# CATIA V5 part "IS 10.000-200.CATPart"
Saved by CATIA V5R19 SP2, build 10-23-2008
Part number: IS 10.000-200
Bounding box of the stored display mesh (mm): x -97.324 to 97.324, y -97.5 to 97.5, z 0 to 560
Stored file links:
  C:\Users\Bora\Desktop\3D Katı model\IS serisi\IS 10.000\IS 10.000-200.CATPart
  C:\Program Files\Dassault Systemes\B19\intel_a\reffiles\standard\MetricThickPitch.txt
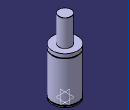
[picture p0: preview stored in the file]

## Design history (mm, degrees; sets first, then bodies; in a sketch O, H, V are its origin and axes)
Body1 (main body)
  Sketch1 on yz-plane, origin (0, 0, 0), H (0, 1, 0), V (0, 0, 1)
    point P1 (97.5, 329)
    point P4 (97.5, 324)
    point P7 (47.5, 559)
    point P9 (47.5, 559)
    point P13 (97.5, 329)
    point P14 (97.5, 324)
    line L1 (97.5, 329) -> (97.5, 357)
    line L2 (97.5, 16) -> (97.5, 324)
    line L3 (93.5, 16) -> (93.5, 8)
    arc A1 centre (46.5, 559) radius 1 from (47.5, 559) to (46.5, 560) ccw
    line L4 (47.5, 559) -> (47.5, 357)
    line L5 (97.5, 0) -> (97.5, 8)
    arc A2 centre (97.5, 326.5) radius 2.5 from (97.5, 329) to (97.5, 324) ccw
    line L6 (46.5, 560) -> (0, 560)
    point P15 (0, 560)
    line L7 (47.5, 357) -> (97.5, 357)
    line L8 (93.5, 16) -> (97.5, 16)
    line L9 (93.5, 8) -> (97.5, 8)
    line L10 (97.5, 0) -> (0, 0)
    coincidence: P15 V, P1 P13, P4 P14, P7 P9
    tangency: L6 A1
    horizontal: L7 H, L8 H, L9 H, L10 H
  Shaft1: profile Sketch1, axis Sketch1.V, angle 360
  Sketch2 on face of Shaft1 from Sketch1.L10, origin (0, 0, 0), H (1, 0, 0), V (0, -1, 0)
    point P1 (60, 0)
    distance P1 V = 60
  Hole1: placed by Sketch2, at (60, 0, 0) direction (0, 0, 1), diameter 10.106, depth 16, threaded "M12", thread diameter 12, thread depth 16, pitch 1.75
  CircPattern1: of Hole1, instances 4, angular step 90, axis from xy-plane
